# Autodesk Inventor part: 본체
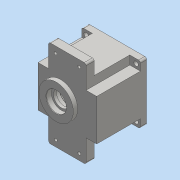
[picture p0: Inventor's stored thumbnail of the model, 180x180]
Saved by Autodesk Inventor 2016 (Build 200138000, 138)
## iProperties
Created: 2020-08
Part Number: 본체
Material: 일반
Document SubType Name: Modeling
Designer: User
Density: 1 g/cm^3
Appearance: 기본값
Mass: 324.61 g
Surface Area: 794.322 cm^2
Volume: 324.61 cm^3
Author: User
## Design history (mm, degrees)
sketch "스케치1"
  geometry: L1 (30, 70)-(-30, 70); L2 (-30, 70)-(-30, -70); L3 (-30, -70)-(30, -70); L4 (30, -70)-(30, 70); L5 (47, 47)-(-47, 47); L6 (-47, 47)-(-47, -47); L7 (-47, -47)-(47, -47); L8 (47, -47)-(47, 47); 5 further points
  constraints: 16 end point, 4 midpoint, 4 parallel, 2 horizontal, 2 horizontal alignment, 2 perpendicular, 2 vertical alignment
  dimensions: "d0" = 60 distance of L2.end L3.end; "d1" = 140 distance of L3.end L1.start; "d2" = 94 distance of L7.end L6.end; "d3" = 94 distance of L6.end L5.end
extrude "돌출1" new body sketch "스케치1" distance "d4" = 13; taper "d5" = 0 deg
sketch "스케치2"
  geometry: L1 (-30, 47)-(-47, 47) reference; L2 (-47, 47)-(-47, -47) reference; L3 (-47, -47)-(-30, -47) reference; L4 (-30, -47)-(-30, -70) reference; L5 (-30, -70)-(30, -70) reference; L6 (30, -70)-(30, -47) reference; L7 (30, -47)-(47, -47) reference; L8 (47, -47)-(47, 47) reference; L9 (47, 47)-(30, 47) reference; L10 (30, 47)-(30, 70) reference; L11 (30, 70)-(-30, 70) reference; L12 (-30, 70)-(-30, 47) reference; L13 (47, -47)-(47, 47) reference; L14 (-47, 47)-(-47, -47) reference; L15 (47, 47)-(-47, 47); L16 (-47, 47)-(-47, -47); L17 (-47, -47)-(47, -47); L18 (47, -47)-(47, 47); 1 further point
  constraints: 8 end point, 2 parallel, 1 horizontal, 1 perpendicular
extrude "돌출2" join sketch "스케치2" distance "d6" = 67; taper "d7" = 0 deg
sketch "스케치3"
  geometry: L1 (-30, -70)-(-30, -47) reference; L2 (30, -70)-(-30, -70) reference; L3 (30, -47)-(30, -70) reference; L4 (47, -47)-(30, -47) reference; L5 (47, 47)-(47, -47) reference; L6 (30, 47)-(47, 47) reference; L7 (30, 70)-(30, 47) reference; L8 (-30, 70)-(30, 70) reference; L9 (-30, 47)-(-30, 70) reference; L10 (-47, 47)-(-30, 47) reference; L11 (-47, -47)-(-47, 47) reference; L12 (-30, -47)-(-47, -47) reference; L13 (47, 47)-(30, 47); L14 (30, 47)-(30, 33); L15 (30, 33)-(47, 33); L16 (47, 33)-(47, 47); L17 (30, 70)-(30, 47) reference; L18 (47, 47)-(47, -47) reference; L19 (47, -47)-(30, -47); L20 (30, -47)-(30, -33); L21 (30, -33)-(47, -33); L22 (47, -33)-(47, -47); L23 (-47, 47)-(-30, 47); L24 (-30, 47)-(-30, 33); L25 (-30, 33)-(-47, 33); L26 (-47, 33)-(-47, 47); L27 (-47, -47)-(-30, -47); L28 (-30, -47)-(-30, -33); L29 (-30, -33)-(-47, -33); L30 (-47, -33)-(-47, -47); L31 (30, -47)-(30, -70) reference; L32 (-30, 47)-(-30, 70) reference; L33 (-30, -70)-(-30, -47) reference; 1 further point
  constraints: 32 end point, 8 parallel, 4 collinear, 4 horizontal, 4 perpendicular, 3 equal length
  dimensions: "d8" = 14 distance of L15.end L5.start
extrude "돌출3" cut sketch "스케치3" distance "d9" = 70; taper "d10" = 0 deg
sketch "스케치4"
  geometry: C1 r 43 at (0, 0); 1 further point
  constraints: 1 centre point, 1 coincident
  dimensions: "d11" = 86 diameter of C1
extrude "돌출4" cut sketch "스케치4" distance "d12" = 9; taper "d13" = 0 deg
sketch "스케치5"
  geometry: C1 r 40 at (0, 0); 1 further point
  constraints: 1 centre point, 1 coincident
  dimensions: "d14" = 80 diameter of C1
extrude "돌출5" cut sketch "스케치5" distance "d15" = 62; taper "d16" = 0 deg
sketch "스케치6"
  geometry: C1 r 21 at (-11, 0); C2 r 15 at (20, 0); 1 further point
  constraints: 2 centre point, 2 horizontal alignment
  dimensions: "d17" = 42 diameter of C1; "d18" = 30 diameter of C2; "d19" = 11 distance of point (0, 0) C1.centre; "d20" = 20 distance of C2.centre point (0, 0)
extrude "돌출6" join sketch "스케치6" distance "d21" = 7; taper "d22" = 0 deg
sketch "스케치7"
  geometry: A1 r 4 centre (0, 36) between (-3.995, 36.19) and (3.995, 36.19); A2 r 4 centre (0, -36) between (3.995, -36.19) and (-3.995, -36.19); A3 r 3 centre (6.992, 36.333) between (7.559, 39.279) and (3.995, 36.19); A4 r 3 centre (-6.992, 36.333) between (-3.995, 36.19) and (-7.559, 39.279); A5 r 3 centre (-6.992, -36.333) between (-7.559, -39.279) and (-3.995, -36.19); A6 r 3 centre (6.992, -36.333) between (3.995, -36.19) and (7.559, -39.279); A7 r 40 centre (0, 0) between (7.559, -39.279) and (-7.559, -39.279) reference; 1 further point
  constraints: 16 point on circle, 8 tangent, 6 centre point, 4 equal radius, 2 vertical alignment
  dimensions: "d23" = 8 diameter of A1; "d24" = 36 distance of A1.centre point (0, 0); "d25" = 36 distance of A2.centre point (0, 0); "d44" = 6 diameter of A3
sketch "스케치8"
  geometry: C1 r 27.5 at (-11, 0); A1 r 21 centre (-11, 0) between (7.984, 8.978) and (7.984, -8.978) reference; A2 r 15 centre (20, 0) between (7.984, -8.978) and (7.984, 8.978) reference; 1 further point
  constraints: 1 centre point, 1 coincident
  dimensions: "d26" = 55 diameter of C1
extrude "돌출7" join sketch "스케치8" distance "d27" = 7; taper "d28" = 0 deg
sketch "스케치9"
  geometry: C1 r 27.5 at (0, 0) reference; C2 r 16 at (0, 0); 1 further point
  constraints: 1 centre point, 1 coincident
  dimensions: "d29" = 32 diameter of C2
extrude "돌출8" cut sketch "스케치9" distance "d30" = 8.3; taper "d31" = 0 deg
sketch "스케치10"
  geometry: C1 r 16 at (0, 0) reference; C2 r 12.5 at (0, 0); 1 further point
  constraints: 1 centre point, 1 coincident
  dimensions: "d32" = 25 diameter of C2
extrude "돌출9" cut sketch "스케치10" distance "d33" = 4.7; taper "d34" = 0 deg
sketch "스케치11"
  geometry: C1 r 12.5 at (0, 0) reference; C2 r 17.5 at (0, 0); 1 further point
  constraints: 1 centre point, 1 coincident
  dimensions: "d35" = 35 diameter of C2
extrude "돌출10" cut sketch "스케치11" distance "d36" = 10; taper "d37" = 0 deg
sketch "스케치12"
  geometry: C1 r 17.5 at (-11, 0) reference; C2 r 11 at (20, 0); A1 r 21 centre (-11, 0) between (7.984, 8.978) and (7.984, -8.978) reference; A2 r 15 centre (20, 0) between (7.984, -8.978) and (7.984, 8.978) reference; 1 further point
  constraints: 1 centre point, 1 coincident
  dimensions: "d38" = 22 diameter of C2
extrude "돌출11" cut sketch "스케치12" distance "d39" = 7; taper "d40" = 0 deg
sketch "스케치13"
  geometry: C1 r 11 at (0, 0) reference; C2 r 9.5 at (0, 0); 1 further point
  constraints: 1 centre point, 1 coincident
  dimensions: "d41" = 19 diameter of C2
extrude "돌출12" cut sketch "스케치13" distance "d42" = 3; taper "d43" = 0 deg
extrude "돌출13" join sketch "스케치7" stored distance "d45" = 3; taper "d46" = 0 deg
chamfer "모따기1" distance "d47" = 0.8; stored, may be unused: second distance "d48" = 2, angle "d49" = 30 deg
fillet "모깎기1" dims "d50" = 3
fillet "모깎기2" dims "d51" = 3
chamfer "모따기2" distance "d52" = 1; stored, may be unused: second distance "d53" = 2, angle "d54" = 45 deg
chamfer "모따기3" distance "d55" = 1; stored, may be unused: second distance "d56" = 2, angle "d57" = 45 deg
sketch "스케치14"
  geometry: 5 further points
  dimensions: "d58" = 60 vertical distance of point (0, 0) point (19, 60); "d59" = 60 vertical distance of point (19, -60) point (0, 0); "d60" = 60 vertical distance of point (0, 0) point (-18.556, 60); "d61" = 60 vertical distance of point (0, 0) point (-19, -60); "d62" = 19 horizontal distance of point (0, 0) point (19, -60); "d63" = 19 horizontal distance of point (-19, -60) point (0, 0); "d64" = 19 horizontal distance of point (19, 60) point (0, 0); "d65" = 18.55564 horizontal distance of point (-18.556, 60) point (0, 0)
hole "구멍1" sketch "스케치14" at (19, -60), (19, 60), (-18.556, 60), (-19, -60) diameter "d66" = 4.5; stored, may be unused: countersink angle "d70" = 90 deg, drill point angle "d72" = 118 deg; dims "d67" = 6, "d68" = 10, "d69" = 5, "d71" = 20
sketch "스케치15"
  geometry: 5 further points
  dimensions: "d73" = 40 horizontal distance of point (0, 0) point (40, 40); "d74" = 40 horizontal distance of point (40, -40) point (0, 0); "d75" = 40 horizontal distance of point (-40, -40) point (0, 0); "d76" = 40 horizontal distance of point (-40, 40) point (0, 0); "d77" = 40 horizontal distance of point (0, 0) point (-40, -40); "d78" = 40 horizontal distance of point (40, -40) point (0, 0); "d79" = 40 horizontal distance of point (40, 40) point (0, 0); "d80" = 40 horizontal distance of point (-40, 40) point (0, 0)
hole "구멍2" sketch "스케치15" at (40, 40), (-40, 40), (-40, -40), (40, -40) diameter "d81" = 7; stored, may be unused: countersink angle "d85" = 90 deg, drill point angle "d87" = 118 deg; dims "d82" = 6, "d83" = 10, "d84" = 5, "d86" = 20
sketch "스케치16"
  geometry: 3 further points
  constraints: 2 vertical alignment
  dimensions: "d88" = 36 distance of point (0, 0) point (0, -36); "d89" = 36 distance of point (0, 36) point (0, 0)
hole "구멍3" sketch "스케치16" at (0, -36), (0, 36) diameter "d90" = 3.242; stored, may be unused: countersink angle "d94" = 90 deg, drill point angle "d96" = 118 deg; dims "d91" = 7, "d92" = 10, "d93" = 5, "d95" = 9
sketch "스케치17"
  geometry: L1 (0, 0)-(66, 0) reference; L2 (-11, 70)-(-11, 80) reference; L3 (-11, 70)-(0, 70) reference; L4 (0, 70)-(0, 0) reference; L5 (0, 0)-(66, 0) reference; L6 (66, 0)-(66, 70) reference; L7 (66, 70)-(77, 70) reference; L8 (77, 80)-(77, 70) reference; L9 (-11, 80)-(77, 80) reference; 3 further points
  constraints: 1 midpoint, 1 vertical alignment, 1 other
  dimensions: "d97" = 40 distance from line of L9 point (33, 40)
feature "엠보싱1" sketch "스케치17" dims "d0" = 60, "d1" = 140, "d2" = 94, "d3" = 94, "d98" = 0.5, "d99" = 0
node "솔리드1"
node "투영된 루프1"
node "투영된 루프2"
node "투영된 루프3"
node "투영된 루프4"
node "투영된 루프5"
node "투영된 루프6"
node "투영된 루프7"
node "투영된 루프8"
node "투영된 루프9"
